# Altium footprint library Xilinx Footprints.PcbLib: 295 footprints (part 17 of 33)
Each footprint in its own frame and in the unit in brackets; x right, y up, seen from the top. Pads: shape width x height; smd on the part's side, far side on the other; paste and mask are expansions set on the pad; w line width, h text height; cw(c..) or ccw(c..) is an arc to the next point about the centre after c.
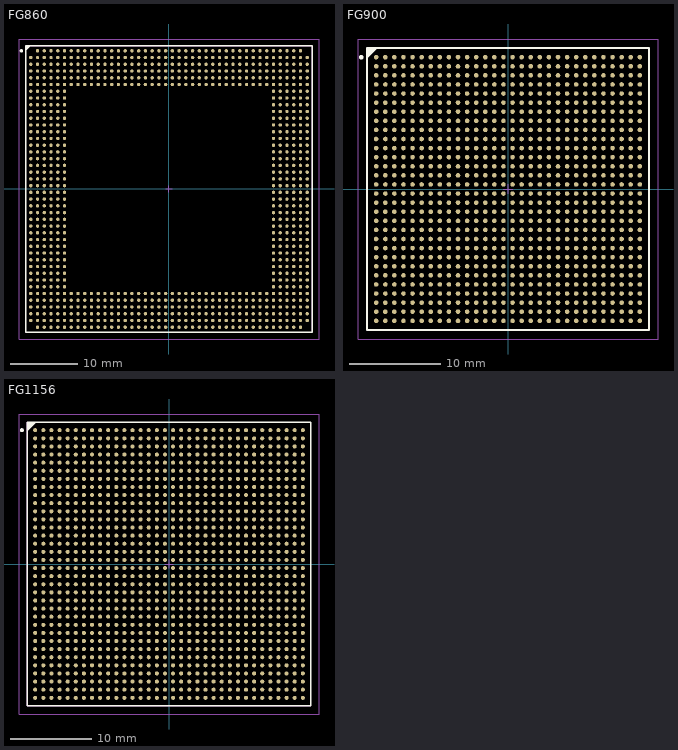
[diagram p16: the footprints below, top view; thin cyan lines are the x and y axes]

## FG860 [mm] "860-Ball Fine Pitch Ball Grid Array (FG860)"
height 2.3
pads (860):
  round 0.5 smd: A2(-19.5,20.5) A3(-18.5,20.5) A4(-17.5,20.5) A5(-16.5,20.5) A6(-15.5,20.5) A7(-14.5,20.5) A8(-13.5,20.5) A9(-12.5,20.5) A10(-11.5,20.5) A11(-10.5,20.5) A12(-9.5,20.5) A13(-8.5,20.5) A14(-7.5,20.5) A15(-6.5,20.5) A16(-5.5,20.5) A17(-4.5,20.5) A18(-3.5,20.5) A19(-2.5,20.5) A20(-1.5,20.5) A21(-0.5,20.5) A22(0.5,20.5) A23(1.5,20.5) A24(2.5,20.5) A25(3.5,20.5) A26(4.5,20.5) A27(5.5,20.5) A28(6.5,20.5) A29(7.5,20.5) A30(8.5,20.5) A31(9.5,20.5) A32(10.5,20.5) A33(11.5,20.5) A34(12.5,20.5) A35(13.5,20.5) A36(14.5,20.5) A37(15.5,20.5) A38(16.5,20.5) A39(17.5,20.5) A40(18.5,20.5) A41(19.5,20.5) AA1(-20.5,0.5) AA2(-19.5,0.5) AA3(-18.5,0.5) AA4(-17.5,0.5) AA5(-16.5,0.5) AA6(-15.5,0.5) AA37(15.5,0.5) AA38(16.5,0.5) AA39(17.5,0.5) AA40(18.5,0.5) AA41(19.5,0.5) AA42(20.5,0.5) AB1(-20.5,-0.5) AB2(-19.5,-0.5) AB3(-18.5,-0.5) AB4(-17.5,-0.5) AB5(-16.5,-0.5) AB6(-15.5,-0.5) AB37(15.5,-0.5) AB38(16.5,-0.5) AB39(17.5,-0.5) AB40(18.5,-0.5) AB41(19.5,-0.5) AB42(20.5,-0.5) AC1(-20.5,-1.5) AC2(-19.5,-1.5) AC3(-18.5,-1.5) AC4(-17.5,-1.5) AC5(-16.5,-1.5) AC6(-15.5,-1.5) AC37(15.5,-1.5) AC38(16.5,-1.5) AC39(17.5,-1.5) AC40(18.5,-1.5) AC41(19.5,-1.5) AC42(20.5,-1.5) AD1(-20.5,-2.5) AD2(-19.5,-2.5) AD3(-18.5,-2.5) AD4(-17.5,-2.5) AD5(-16.5,-2.5) AD6(-15.5,-2.5) AD37(15.5,-2.5) AD38(16.5,-2.5) AD39(17.5,-2.5) AD40(18.5,-2.5) AD41(19.5,-2.5) AD42(20.5,-2.5) AE1(-20.5,-3.5) AE2(-19.5,-3.5) AE3(-18.5,-3.5) AE4(-17.5,-3.5) AE5(-16.5,-3.5) AE6(-15.5,-3.5) AE37(15.5,-3.5) AE38(16.5,-3.5) AE39(17.5,-3.5) AE40(18.5,-3.5) AE41(19.5,-3.5) AE42(20.5,-3.5) AF1(-20.5,-4.5) AF2(-19.5,-4.5) AF3(-18.5,-4.5) AF4(-17.5,-4.5) AF5(-16.5,-4.5) AF6(-15.5,-4.5) AF37(15.5,-4.5) AF38(16.5,-4.5) AF39(17.5,-4.5) AF40(18.5,-4.5) AF41(19.5,-4.5) AF42(20.5,-4.5) AG1(-20.5,-5.5) AG2(-19.5,-5.5) AG3(-18.5,-5.5) AG4(-17.5,-5.5) AG5(-16.5,-5.5) AG6(-15.5,-5.5) AG37(15.5,-5.5) AG38(16.5,-5.5) AG39(17.5,-5.5) AG40(18.5,-5.5) AG41(19.5,-5.5) AG42(20.5,-5.5) AH1(-20.5,-6.5) AH2(-19.5,-6.5) AH3(-18.5,-6.5) AH4(-17.5,-6.5) AH5(-16.5,-6.5) AH6(-15.5,-6.5) AH37(15.5,-6.5) AH38(16.5,-6.5) AH39(17.5,-6.5) AH40(18.5,-6.5) AH41(19.5,-6.5) AH42(20.5,-6.5) AJ1(-20.5,-7.5) AJ2(-19.5,-7.5) AJ3(-18.5,-7.5) AJ4(-17.5,-7.5) AJ5(-16.5,-7.5) AJ6(-15.5,-7.5) AJ37(15.5,-7.5) AJ38(16.5,-7.5) AJ39(17.5,-7.5) AJ40(18.5,-7.5) AJ41(19.5,-7.5) AJ42(20.5,-7.5) AK1(-20.5,-8.5) AK2(-19.5,-8.5) AK3(-18.5,-8.5) AK4(-17.5,-8.5) AK5(-16.5,-8.5) AK6(-15.5,-8.5) AK37(15.5,-8.5) AK38(16.5,-8.5) AK39(17.5,-8.5) AK40(18.5,-8.5) AK41(19.5,-8.5) AK42(20.5,-8.5) AL1(-20.5,-9.5) AL2(-19.5,-9.5) AL3(-18.5,-9.5) AL4(-17.5,-9.5) AL5(-16.5,-9.5) AL6(-15.5,-9.5) AL37(15.5,-9.5) AL38(16.5,-9.5) AL39(17.5,-9.5) AL40(18.5,-9.5) AL41(19.5,-9.5) AL42(20.5,-9.5) AM1(-20.5,-10.5) AM2(-19.5,-10.5) AM3(-18.5,-10.5) AM4(-17.5,-10.5) AM5(-16.5,-10.5) AM6(-15.5,-10.5) AM37(15.5,-10.5) AM38(16.5,-10.5) AM39(17.5,-10.5) AM40(18.5,-10.5) AM41(19.5,-10.5) AM42(20.5,-10.5) AN1(-20.5,-11.5) AN2(-19.5,-11.5) AN3(-18.5,-11.5) AN4(-17.5,-11.5) AN5(-16.5,-11.5) AN6(-15.5,-11.5) AN37(15.5,-11.5) AN38(16.5,-11.5) AN39(17.5,-11.5) AN40(18.5,-11.5) AN41(19.5,-11.5) AN42(20.5,-11.5) AP1(-20.5,-12.5) AP2(-19.5,-12.5) AP3(-18.5,-12.5) AP4(-17.5,-12.5) AP5(-16.5,-12.5) AP6(-15.5,-12.5) AP37(15.5,-12.5) AP38(16.5,-12.5) AP39(17.5,-12.5) AP40(18.5,-12.5) AP41(19.5,-12.5) AP42(20.5,-12.5) AR1(-20.5,-13.5) AR2(-19.5,-13.5) AR3(-18.5,-13.5) AR4(-17.5,-13.5) AR5(-16.5,-13.5) AR6(-15.5,-13.5) AR37(15.5,-13.5) AR38(16.5,-13.5) AR39(17.5,-13.5) AR40(18.5,-13.5) AR41(19.5,-13.5) AR42(20.5,-13.5) AT1(-20.5,-14.5) AT2(-19.5,-14.5) AT3(-18.5,-14.5) AT4(-17.5,-14.5) AT5(-16.5,-14.5) AT6(-15.5,-14.5) AT37(15.5,-14.5) AT38(16.5,-14.5) AT39(17.5,-14.5) AT40(18.5,-14.5) AT41(19.5,-14.5) AT42(20.5,-14.5) AU1(-20.5,-15.5) AU2(-19.5,-15.5) AU3(-18.5,-15.5) AU4(-17.5,-15.5) AU5(-16.5,-15.5) AU6(-15.5,-15.5) AU7(-14.5,-15.5) AU8(-13.5,-15.5) AU9(-12.5,-15.5) AU10(-11.5,-15.5) AU11(-10.5,-15.5) AU12(-9.5,-15.5) AU13(-8.5,-15.5) AU14(-7.5,-15.5) AU15(-6.5,-15.5) AU16(-5.5,-15.5) AU17(-4.5,-15.5) AU18(-3.5,-15.5) AU19(-2.5,-15.5) AU20(-1.5,-15.5) AU21(-0.5,-15.5) AU22(0.5,-15.5) AU23(1.5,-15.5) AU24(2.5,-15.5) AU25(3.5,-15.5) AU26(4.5,-15.5) AU27(5.5,-15.5) AU28(6.5,-15.5) AU29(7.5,-15.5) AU30(8.5,-15.5) AU31(9.5,-15.5) AU32(10.5,-15.5) AU33(11.5,-15.5) AU34(12.5,-15.5) AU35(13.5,-15.5) AU36(14.5,-15.5) AU37(15.5,-15.5) AU38(16.5,-15.5) AU39(17.5,-15.5) AU40(18.5,-15.5) AU41(19.5,-15.5) AU42(20.5,-15.5) AV1(-20.5,-16.5) AV2(-19.5,-16.5) AV3(-18.5,-16.5) AV4(-17.5,-16.5) AV5(-16.5,-16.5) AV6(-15.5,-16.5) AV7(-14.5,-16.5) AV8(-13.5,-16.5) AV9(-12.5,-16.5) AV10(-11.5,-16.5) AV11(-10.5,-16.5) AV12(-9.5,-16.5) AV13(-8.5,-16.5) AV14(-7.5,-16.5) AV15(-6.5,-16.5) AV16(-5.5,-16.5) AV17(-4.5,-16.5) AV18(-3.5,-16.5) AV19(-2.5,-16.5) AV20(-1.5,-16.5) AV21(-0.5,-16.5) AV22(0.5,-16.5) AV23(1.5,-16.5) AV24(2.5,-16.5) AV25(3.5,-16.5) AV26(4.5,-16.5) AV27(5.5,-16.5) AV28(6.5,-16.5) AV29(7.5,-16.5) AV30(8.5,-16.5) AV31(9.5,-16.5) AV32(10.5,-16.5) AV33(11.5,-16.5) AV34(12.5,-16.5) AV35(13.5,-16.5) AV36(14.5,-16.5) AV37(15.5,-16.5) AV38(16.5,-16.5) AV39(17.5,-16.5) AV40(18.5,-16.5) AV41(19.5,-16.5) AV42(20.5,-16.5) AW1(-20.5,-17.5) AW2(-19.5,-17.5) AW3(-18.5,-17.5) AW4(-17.5,-17.5) AW5(-16.5,-17.5) AW6(-15.5,-17.5) AW7(-14.5,-17.5) AW8(-13.5,-17.5) AW9(-12.5,-17.5) AW10(-11.5,-17.5) AW11(-10.5,-17.5) AW12(-9.5,-17.5) AW13(-8.5,-17.5) AW14(-7.5,-17.5) AW15(-6.5,-17.5) AW16(-5.5,-17.5) AW17(-4.5,-17.5) AW18(-3.5,-17.5) AW19(-2.5,-17.5) AW20(-1.5,-17.5) AW21(-0.5,-17.5) AW22(0.5,-17.5) AW23(1.5,-17.5) AW24(2.5,-17.5) AW25(3.5,-17.5) AW26(4.5,-17.5) AW27(5.5,-17.5) AW28(6.5,-17.5) AW29(7.5,-17.5) AW30(8.5,-17.5) AW31(9.5,-17.5) AW32(10.5,-17.5) AW33(11.5,-17.5) AW34(12.5,-17.5) AW35(13.5,-17.5) AW36(14.5,-17.5) AW37(15.5,-17.5) AW38(16.5,-17.5) AW39(17.5,-17.5) AW40(18.5,-17.5) AW41(19.5,-17.5) AW42(20.5,-17.5) AY1(-20.5,-18.5) AY2(-19.5,-18.5) AY3(-18.5,-18.5) AY4(-17.5,-18.5) AY5(-16.5,-18.5) AY6(-15.5,-18.5) AY7(-14.5,-18.5) AY8(-13.5,-18.5) AY9(-12.5,-18.5) AY10(-11.5,-18.5) AY11(-10.5,-18.5) AY12(-9.5,-18.5) AY13(-8.5,-18.5) AY14(-7.5,-18.5) AY15(-6.5,-18.5) AY16(-5.5,-18.5) AY17(-4.5,-18.5) AY18(-3.5,-18.5) AY19(-2.5,-18.5) AY20(-1.5,-18.5) AY21(-0.5,-18.5) AY22(0.5,-18.5) AY23(1.5,-18.5) AY24(2.5,-18.5) AY25(3.5,-18.5) AY26(4.5,-18.5) AY27(5.5,-18.5) AY28(6.5,-18.5) AY29(7.5,-18.5) AY30(8.5,-18.5) AY31(9.5,-18.5) AY32(10.5,-18.5) AY33(11.5,-18.5) AY34(12.5,-18.5) AY35(13.5,-18.5) AY36(14.5,-18.5) AY37(15.5,-18.5) AY38(16.5,-18.5) AY39(17.5,-18.5) AY40(18.5,-18.5) AY41(19.5,-18.5) AY42(20.5,-18.5) B1(-20.5,19.5) B2(-19.5,19.5) B3(-18.5,19.5) B4(-17.5,19.5) B5(-16.5,19.5) B6(-15.5,19.5) B7(-14.5,19.5) B8(-13.5,19.5) B9(-12.5,19.5) B10(-11.5,19.5) B11(-10.5,19.5) B12(-9.5,19.5) B13(-8.5,19.5) B14(-7.5,19.5) B15(-6.5,19.5) B16(-5.5,19.5) B17(-4.5,19.5) B18(-3.5,19.5) B19(-2.5,19.5) B20(-1.5,19.5) B21(-0.5,19.5) B22(0.5,19.5) B23(1.5,19.5) B24(2.5,19.5) B25(3.5,19.5) B26(4.5,19.5) B27(5.5,19.5) B28(6.5,19.5) B29(7.5,19.5) B30(8.5,19.5) B31(9.5,19.5) B32(10.5,19.5) B33(11.5,19.5) B34(12.5,19.5) B35(13.5,19.5) B36(14.5,19.5) B37(15.5,19.5) B38(16.5,19.5) B39(17.5,19.5) B40(18.5,19.5) B41(19.5,19.5) B42(20.5,19.5) BA1(-20.5,-19.5) BA2(-19.5,-19.5) BA3(-18.5,-19.5) BA4(-17.5,-19.5) BA5(-16.5,-19.5) BA6(-15.5,-19.5) BA7(-14.5,-19.5) BA8(-13.5,-19.5) BA9(-12.5,-19.5) BA10(-11.5,-19.5) BA11(-10.5,-19.5) BA12(-9.5,-19.5) BA13(-8.5,-19.5) BA14(-7.5,-19.5) BA15(-6.5,-19.5) BA16(-5.5,-19.5) BA17(-4.5,-19.5) BA18(-3.5,-19.5) BA19(-2.5,-19.5) BA20(-1.5,-19.5) BA21(-0.5,-19.5) BA22(0.5,-19.5) BA23(1.5,-19.5) BA24(2.5,-19.5) BA25(3.5,-19.5) BA26(4.5,-19.5) BA27(5.5,-19.5) BA28(6.5,-19.5) BA29(7.5,-19.5) BA30(8.5,-19.5) BA31(9.5,-19.5) BA32(10.5,-19.5) BA33(11.5,-19.5) BA34(12.5,-19.5) BA35(13.5,-19.5) BA36(14.5,-19.5) BA37(15.5,-19.5) BA38(16.5,-19.5) BA39(17.5,-19.5) BA40(18.5,-19.5) BA41(19.5,-19.5) BA42(20.5,-19.5) BB2(-19.5,-20.5) BB3(-18.5,-20.5) BB4(-17.5,-20.5) BB5(-16.5,-20.5) BB6(-15.5,-20.5) BB7(-14.5,-20.5) BB8(-13.5,-20.5) BB9(-12.5,-20.5) BB10(-11.5,-20.5) BB11(-10.5,-20.5) BB12(-9.5,-20.5) BB13(-8.5,-20.5) BB14(-7.5,-20.5) BB15(-6.5,-20.5) BB16(-5.5,-20.5) BB17(-4.5,-20.5) BB18(-3.5,-20.5) BB19(-2.5,-20.5) BB20(-1.5,-20.5) BB21(-0.5,-20.5) BB22(0.5,-20.5) BB23(1.5,-20.5) BB24(2.5,-20.5) BB25(3.5,-20.5) BB26(4.5,-20.5) BB27(5.5,-20.5) BB28(6.5,-20.5) BB29(7.5,-20.5) BB30(8.5,-20.5) BB31(9.5,-20.5) BB32(10.5,-20.5) BB33(11.5,-20.5) BB34(12.5,-20.5) BB35(13.5,-20.5) BB36(14.5,-20.5) BB37(15.5,-20.5) BB38(16.5,-20.5) BB39(17.5,-20.5) BB40(18.5,-20.5) BB41(19.5,-20.5) C1(-20.5,18.5) C2(-19.5,18.5) C3(-18.5,18.5) C4(-17.5,18.5) C5(-16.5,18.5) C6(-15.5,18.5) C7(-14.5,18.5) C8(-13.5,18.5) C9(-12.5,18.5) C10(-11.5,18.5) C11(-10.5,18.5) C12(-9.5,18.5) C13(-8.5,18.5) C14(-7.5,18.5) C15(-6.5,18.5) C16(-5.5,18.5) C17(-4.5,18.5) C18(-3.5,18.5) C19(-2.5,18.5) C20(-1.5,18.5) C21(-0.5,18.5) C22(0.5,18.5) C23(1.5,18.5) C24(2.5,18.5) C25(3.5,18.5) C26(4.5,18.5) C27(5.5,18.5) C28(6.5,18.5) C29(7.5,18.5) C30(8.5,18.5) C31(9.5,18.5) C32(10.5,18.5) C33(11.5,18.5) C34(12.5,18.5) C35(13.5,18.5) C36(14.5,18.5) C37(15.5,18.5) C38(16.5,18.5) C39(17.5,18.5) C40(18.5,18.5) C41(19.5,18.5) C42(20.5,18.5) D1(-20.5,17.5) D2(-19.5,17.5) D3(-18.5,17.5) D4(-17.5,17.5) D5(-16.5,17.5) D6(-15.5,17.5) D7(-14.5,17.5) D8(-13.5,17.5) D9(-12.5,17.5) D10(-11.5,17.5) D11(-10.5,17.5) D12(-9.5,17.5) D13(-8.5,17.5) D14(-7.5,17.5) D15(-6.5,17.5) D16(-5.5,17.5) D17(-4.5,17.5) D18(-3.5,17.5) D19(-2.5,17.5) D20(-1.5,17.5) D21(-0.5,17.5) D22(0.5,17.5) D23(1.5,17.5) D24(2.5,17.5) D25(3.5,17.5) D26(4.5,17.5) D27(5.5,17.5) D28(6.5,17.5) D29(7.5,17.5) D30(8.5,17.5) D31(9.5,17.5) D32(10.5,17.5) D33(11.5,17.5) D34(12.5,17.5) D35(13.5,17.5) D36(14.5,17.5) D37(15.5,17.5) D38(16.5,17.5) D39(17.5,17.5) D40(18.5,17.5) D41(19.5,17.5) D42(20.5,17.5) E1(-20.5,16.5) E2(-19.5,16.5) E3(-18.5,16.5) E4(-17.5,16.5) E5(-16.5,16.5) E6(-15.5,16.5) E7(-14.5,16.5) E8(-13.5,16.5) E9(-12.5,16.5) E10(-11.5,16.5) E11(-10.5,16.5) E12(-9.5,16.5) E13(-8.5,16.5) E14(-7.5,16.5) E15(-6.5,16.5) E16(-5.5,16.5) E17(-4.5,16.5) E18(-3.5,16.5) E19(-2.5,16.5) E20(-1.5,16.5) E21(-0.5,16.5) E22(0.5,16.5) E23(1.5,16.5) E24(2.5,16.5) E25(3.5,16.5) E26(4.5,16.5) E27(5.5,16.5) E28(6.5,16.5) E29(7.5,16.5) E30(8.5,16.5) E31(9.5,16.5) E32(10.5,16.5) E33(11.5,16.5) E34(12.5,16.5) E35(13.5,16.5) E36(14.5,16.5) E37(15.5,16.5) E38(16.5,16.5) E39(17.5,16.5) E40(18.5,16.5) E41(19.5,16.5) E42(20.5,16.5) F1(-20.5,15.5) F2(-19.5,15.5) F3(-18.5,15.5) F4(-17.5,15.5) F5(-16.5,15.5) F6(-15.5,15.5) F7(-14.5,15.5) F8(-13.5,15.5) F9(-12.5,15.5) F10(-11.5,15.5) F11(-10.5,15.5) F12(-9.5,15.5) F13(-8.5,15.5) F14(-7.5,15.5) F15(-6.5,15.5) F16(-5.5,15.5) F17(-4.5,15.5) F18(-3.5,15.5) F19(-2.5,15.5) F20(-1.5,15.5) F21(-0.5,15.5) F22(0.5,15.5) F23(1.5,15.5) F24(2.5,15.5) F25(3.5,15.5) F26(4.5,15.5) F27(5.5,15.5) F28(6.5,15.5) F29(7.5,15.5) F30(8.5,15.5) F31(9.5,15.5) F32(10.5,15.5) F33(11.5,15.5) F34(12.5,15.5) F35(13.5,15.5) F36(14.5,15.5) F37(15.5,15.5) F38(16.5,15.5) F39(17.5,15.5) F40(18.5,15.5) F41(19.5,15.5) F42(20.5,15.5) G1(-20.5,14.5) G2(-19.5,14.5) G3(-18.5,14.5) G4(-17.5,14.5) G5(-16.5,14.5) G6(-15.5,14.5) G37(15.5,14.5) G38(16.5,14.5) G39(17.5,14.5) G40(18.5,14.5) G41(19.5,14.5) G42(20.5,14.5) H1(-20.5,13.5) H2(-19.5,13.5) H3(-18.5,13.5) H4(-17.5,13.5) H5(-16.5,13.5) H6(-15.5,13.5) H37(15.5,13.5) H38(16.5,13.5) H39(17.5,13.5) H40(18.5,13.5) H41(19.5,13.5) H42(20.5,13.5) J1(-20.5,12.5) J2(-19.5,12.5) J3(-18.5,12.5) J4(-17.5,12.5) J5(-16.5,12.5) J6(-15.5,12.5) J37(15.5,12.5) J38(16.5,12.5) J39(17.5,12.5) J40(18.5,12.5) J41(19.5,12.5) J42(20.5,12.5) K1(-20.5,11.5) K2(-19.5,11.5) K3(-18.5,11.5) K4(-17.5,11.5) K5(-16.5,11.5) K6(-15.5,11.5) K37(15.5,11.5) K38(16.5,11.5) K39(17.5,11.5) K40(18.5,11.5) K41(19.5,11.5) K42(20.5,11.5) L1(-20.5,10.5) L2(-19.5,10.5) L3(-18.5,10.5) L4(-17.5,10.5) L5(-16.5,10.5) L6(-15.5,10.5) L37(15.5,10.5) L38(16.5,10.5) L39(17.5,10.5) L40(18.5,10.5) L41(19.5,10.5) L42(20.5,10.5) M1(-20.5,9.5) M2(-19.5,9.5) M3(-18.5,9.5) M4(-17.5,9.5) M5(-16.5,9.5) M6(-15.5,9.5) M37(15.5,9.5) M38(16.5,9.5) M39(17.5,9.5) M40(18.5,9.5) M41(19.5,9.5) M42(20.5,9.5) N1(-20.5,8.5) N2(-19.5,8.5) N3(-18.5,8.5) N4(-17.5,8.5) N5(-16.5,8.5) N6(-15.5,8.5) N37(15.5,8.5) N38(16.5,8.5) N39(17.5,8.5) N40(18.5,8.5) N41(19.5,8.5) N42(20.5,8.5) P1(-20.5,7.5) P2(-19.5,7.5) P3(-18.5,7.5) P4(-17.5,7.5) P5(-16.5,7.5) P6(-15.5,7.5) P37(15.5,7.5) P38(16.5,7.5) P39(17.5,7.5) P40(18.5,7.5) P41(19.5,7.5) P42(20.5,7.5) R1(-20.5,6.5) R2(-19.5,6.5) R3(-18.5,6.5) R4(-17.5,6.5) R5(-16.5,6.5) R6(-15.5,6.5) R37(15.5,6.5) R38(16.5,6.5) R39(17.5,6.5) R40(18.5,6.5) R41(19.5,6.5) R42(20.5,6.5) T1(-20.5,5.5) T2(-19.5,5.5) T3(-18.5,5.5) T4(-17.5,5.5) T5(-16.5,5.5) T6(-15.5,5.5) T37(15.5,5.5) T38(16.5,5.5) T39(17.5,5.5) T40(18.5,5.5) T41(19.5,5.5) T42(20.5,5.5) U1(-20.5,4.5) U2(-19.5,4.5) U3(-18.5,4.5) U4(-17.5,4.5) U5(-16.5,4.5) U6(-15.5,4.5) U37(15.5,4.5) U38(16.5,4.5) U39(17.5,4.5) U40(18.5,4.5) U41(19.5,4.5) U42(20.5,4.5) V1(-20.5,3.5) V2(-19.5,3.5) V3(-18.5,3.5) V4(-17.5,3.5) V5(-16.5,3.5) V6(-15.5,3.5) V37(15.5,3.5) V38(16.5,3.5) V39(17.5,3.5) V40(18.5,3.5) V41(19.5,3.5) V42(20.5,3.5) W1(-20.5,2.5) W2(-19.5,2.5) W3(-18.5,2.5) W4(-17.5,2.5) W5(-16.5,2.5) W6(-15.5,2.5) W37(15.5,2.5) W38(16.5,2.5) W39(17.5,2.5) W40(18.5,2.5) W41(19.5,2.5) W42(20.5,2.5) Y1(-20.5,1.5) Y2(-19.5,1.5) Y3(-18.5,1.5) Y4(-17.5,1.5) Y5(-16.5,1.5) Y6(-15.5,1.5) Y37(15.5,1.5) Y38(16.5,1.5) Y39(17.5,1.5) Y40(18.5,1.5) Y41(19.5,1.5) Y42(20.5,1.5)
Top Overlay:
  circle w0.25: c-21.9,20.5 r0.125
  region: -20.669,21.25 -21.25,20.669 -21.25,21.25
  lines w0.2: -21.25,20.669 -20.669,21.25 ; -21.25,-21.25 21.25,-21.25 21.25,21.25 -21.25,21.25 -21.25,-21.25
Mechanical 13:
  lines w0.1: -21.25,-21.25 21.25,-21.25 21.25,21.25 -21.25,21.25 -21.25,-21.25
Mechanical 15:
  lines w0.1: -0.5,0 0.5,0 ; 0,-0.5 0,0.5 ; -22.25,-22.25 22.25,-22.25 22.25,22.25 -22.25,22.25 -22.25,-22.25
3D body: height 2.3, standoff 0, extent -21.25,-21.25 21.25,21.25

## FG900 [mm] "900-Ball Fine Pitch Ball Grid Array (FG900)"
height 2.6
pads (900):
  round 0.5 smd: A1(-14.5,14.5) A2(-13.5,14.5) A3(-12.5,14.5) A4(-11.5,14.5) A5(-10.5,14.5) A6(-9.5,14.5) A7(-8.5,14.5) A8(-7.5,14.5) A9(-6.5,14.5) A10(-5.5,14.5) A11(-4.5,14.5) A12(-3.5,14.5) A13(-2.5,14.5) A14(-1.5,14.5) A15(-0.5,14.5) A16(0.5,14.5) A17(1.5,14.5) A18(2.5,14.5) A19(3.5,14.5) A20(4.5,14.5) A21(5.5,14.5) A22(6.5,14.5) A23(7.5,14.5) A24(8.5,14.5) A25(9.5,14.5) A26(10.5,14.5) A27(11.5,14.5) A28(12.5,14.5) A29(13.5,14.5) A30(14.5,14.5) AA1(-14.5,-5.5) AA2(-13.5,-5.5) AA3(-12.5,-5.5) AA4(-11.5,-5.5) AA5(-10.5,-5.5) AA6(-9.5,-5.5) AA7(-8.5,-5.5) AA8(-7.5,-5.5) AA9(-6.5,-5.5) AA10(-5.5,-5.5) AA11(-4.5,-5.5) AA12(-3.5,-5.5) AA13(-2.5,-5.5) AA14(-1.5,-5.5) AA15(-0.5,-5.5) AA16(0.5,-5.5) AA17(1.5,-5.5) AA18(2.5,-5.5) AA19(3.5,-5.5) AA20(4.5,-5.5) AA21(5.5,-5.5) AA22(6.5,-5.5) AA23(7.5,-5.5) AA24(8.5,-5.5) AA25(9.5,-5.5) AA26(10.5,-5.5) AA27(11.5,-5.5) AA28(12.5,-5.5) AA29(13.5,-5.5) AA30(14.5,-5.5) AB1(-14.5,-6.5) AB2(-13.5,-6.5) AB3(-12.5,-6.5) AB4(-11.5,-6.5) AB5(-10.5,-6.5) AB6(-9.5,-6.5) AB7(-8.5,-6.5) AB8(-7.5,-6.5) AB9(-6.5,-6.5) AB10(-5.5,-6.5) AB11(-4.5,-6.5) AB12(-3.5,-6.5) AB13(-2.5,-6.5) AB14(-1.5,-6.5) AB15(-0.5,-6.5) AB16(0.5,-6.5) AB17(1.5,-6.5) AB18(2.5,-6.5) AB19(3.5,-6.5) AB20(4.5,-6.5) AB21(5.5,-6.5) AB22(6.5,-6.5) AB23(7.5,-6.5) AB24(8.5,-6.5) AB25(9.5,-6.5) AB26(10.5,-6.5) AB27(11.5,-6.5) AB28(12.5,-6.5) AB29(13.5,-6.5) AB30(14.5,-6.5) AC1(-14.5,-7.5) AC2(-13.5,-7.5) AC3(-12.5,-7.5) AC4(-11.5,-7.5) AC5(-10.5,-7.5) AC6(-9.5,-7.5) AC7(-8.5,-7.5) AC8(-7.5,-7.5) AC9(-6.5,-7.5) AC10(-5.5,-7.5) AC11(-4.5,-7.5) AC12(-3.5,-7.5) AC13(-2.5,-7.5) AC14(-1.5,-7.5) AC15(-0.5,-7.5) AC16(0.5,-7.5) AC17(1.5,-7.5) AC18(2.5,-7.5) AC19(3.5,-7.5) AC20(4.5,-7.5) AC21(5.5,-7.5) AC22(6.5,-7.5) AC23(7.5,-7.5) AC24(8.5,-7.5) AC25(9.5,-7.5) AC26(10.5,-7.5) AC27(11.5,-7.5) AC28(12.5,-7.5) AC29(13.5,-7.5) AC30(14.5,-7.5) AD1(-14.5,-8.5) AD2(-13.5,-8.5) AD3(-12.5,-8.5) AD4(-11.5,-8.5) AD5(-10.5,-8.5) AD6(-9.5,-8.5) AD7(-8.5,-8.5) AD8(-7.5,-8.5) AD9(-6.5,-8.5) AD10(-5.5,-8.5) AD11(-4.5,-8.5) AD12(-3.5,-8.5) AD13(-2.5,-8.5) AD14(-1.5,-8.5) AD15(-0.5,-8.5) AD16(0.5,-8.5) AD17(1.5,-8.5) AD18(2.5,-8.5) AD19(3.5,-8.5) AD20(4.5,-8.5) AD21(5.5,-8.5) AD22(6.5,-8.5) AD23(7.5,-8.5) AD24(8.5,-8.5) AD25(9.5,-8.5) AD26(10.5,-8.5) AD27(11.5,-8.5) AD28(12.5,-8.5) AD29(13.5,-8.5) AD30(14.5,-8.5) AE1(-14.5,-9.5) AE2(-13.5,-9.5) AE3(-12.5,-9.5) AE4(-11.5,-9.5) AE5(-10.5,-9.5) AE6(-9.5,-9.5) AE7(-8.5,-9.5) AE8(-7.5,-9.5) AE9(-6.5,-9.5) AE10(-5.5,-9.5) AE11(-4.5,-9.5) AE12(-3.5,-9.5) AE13(-2.5,-9.5) AE14(-1.5,-9.5) AE15(-0.5,-9.5) AE16(0.5,-9.5) AE17(1.5,-9.5) AE18(2.5,-9.5) AE19(3.5,-9.5) AE20(4.5,-9.5) AE21(5.5,-9.5) AE22(6.5,-9.5) AE23(7.5,-9.5) AE24(8.5,-9.5) AE25(9.5,-9.5) AE26(10.5,-9.5) AE27(11.5,-9.5) AE28(12.5,-9.5) AE29(13.5,-9.5) AE30(14.5,-9.5) AF1(-14.5,-10.5) AF2(-13.5,-10.5) AF3(-12.5,-10.5) AF4(-11.5,-10.5) AF5(-10.5,-10.5) AF6(-9.5,-10.5) AF7(-8.5,-10.5) AF8(-7.5,-10.5) AF9(-6.5,-10.5) AF10(-5.5,-10.5) AF11(-4.5,-10.5) AF12(-3.5,-10.5) AF13(-2.5,-10.5) AF14(-1.5,-10.5) AF15(-0.5,-10.5) AF16(0.5,-10.5) AF17(1.5,-10.5) AF18(2.5,-10.5) AF19(3.5,-10.5) AF20(4.5,-10.5) AF21(5.5,-10.5) AF22(6.5,-10.5) AF23(7.5,-10.5) AF24(8.5,-10.5) AF25(9.5,-10.5) AF26(10.5,-10.5) AF27(11.5,-10.5) AF28(12.5,-10.5) AF29(13.5,-10.5) AF30(14.5,-10.5) AG1(-14.5,-11.5) AG2(-13.5,-11.5) AG3(-12.5,-11.5) AG4(-11.5,-11.5) AG5(-10.5,-11.5) AG6(-9.5,-11.5) AG7(-8.5,-11.5) AG8(-7.5,-11.5) AG9(-6.5,-11.5) AG10(-5.5,-11.5) AG11(-4.5,-11.5) AG12(-3.5,-11.5) AG13(-2.5,-11.5) AG14(-1.5,-11.5) AG15(-0.5,-11.5) AG16(0.5,-11.5) AG17(1.5,-11.5) AG18(2.5,-11.5) AG19(3.5,-11.5) AG20(4.5,-11.5) AG21(5.5,-11.5) AG22(6.5,-11.5) AG23(7.5,-11.5) AG24(8.5,-11.5) AG25(9.5,-11.5) AG26(10.5,-11.5) AG27(11.5,-11.5) AG28(12.5,-11.5) AG29(13.5,-11.5) AG30(14.5,-11.5) AH1(-14.5,-12.5) AH2(-13.5,-12.5) AH3(-12.5,-12.5) AH4(-11.5,-12.5) AH5(-10.5,-12.5) AH6(-9.5,-12.5) AH7(-8.5,-12.5) AH8(-7.5,-12.5) AH9(-6.5,-12.5) AH10(-5.5,-12.5) AH11(-4.5,-12.5) AH12(-3.5,-12.5) AH13(-2.5,-12.5) AH14(-1.5,-12.5) AH15(-0.5,-12.5) AH16(0.5,-12.5) AH17(1.5,-12.5) AH18(2.5,-12.5) AH19(3.5,-12.5) AH20(4.5,-12.5) AH21(5.5,-12.5) AH22(6.5,-12.5) AH23(7.5,-12.5) AH24(8.5,-12.5) AH25(9.5,-12.5) AH26(10.5,-12.5) AH27(11.5,-12.5) AH28(12.5,-12.5) AH29(13.5,-12.5) AH30(14.5,-12.5) AJ1(-14.5,-13.5) AJ2(-13.5,-13.5) AJ3(-12.5,-13.5) AJ4(-11.5,-13.5) AJ5(-10.5,-13.5) AJ6(-9.5,-13.5) AJ7(-8.5,-13.5) AJ8(-7.5,-13.5) AJ9(-6.5,-13.5) AJ10(-5.5,-13.5) AJ11(-4.5,-13.5) AJ12(-3.5,-13.5) AJ13(-2.5,-13.5) AJ14(-1.5,-13.5) AJ15(-0.5,-13.5) AJ16(0.5,-13.5) AJ17(1.5,-13.5) AJ18(2.5,-13.5) AJ19(3.5,-13.5) AJ20(4.5,-13.5) AJ21(5.5,-13.5) AJ22(6.5,-13.5) AJ23(7.5,-13.5) AJ24(8.5,-13.5) AJ25(9.5,-13.5) AJ26(10.5,-13.5) AJ27(11.5,-13.5) AJ28(12.5,-13.5) AJ29(13.5,-13.5) AJ30(14.5,-13.5) AK1(-14.5,-14.5) AK2(-13.5,-14.5) AK3(-12.5,-14.5) AK4(-11.5,-14.5) AK5(-10.5,-14.5) AK6(-9.5,-14.5) AK7(-8.5,-14.5) AK8(-7.5,-14.5) AK9(-6.5,-14.5) AK10(-5.5,-14.5) AK11(-4.5,-14.5) AK12(-3.5,-14.5) AK13(-2.5,-14.5) AK14(-1.5,-14.5) AK15(-0.5,-14.5) AK16(0.5,-14.5) AK17(1.5,-14.5) AK18(2.5,-14.5) AK19(3.5,-14.5) AK20(4.5,-14.5) AK21(5.5,-14.5) AK22(6.5,-14.5) AK23(7.5,-14.5) AK24(8.5,-14.5) AK25(9.5,-14.5) AK26(10.5,-14.5) AK27(11.5,-14.5) AK28(12.5,-14.5) AK29(13.5,-14.5) AK30(14.5,-14.5) B1(-14.5,13.5) B2(-13.5,13.5) B3(-12.5,13.5) B4(-11.5,13.5) B5(-10.5,13.5) B6(-9.5,13.5) B7(-8.5,13.5) B8(-7.5,13.5) B9(-6.5,13.5) B10(-5.5,13.5) B11(-4.5,13.5) B12(-3.5,13.5) B13(-2.5,13.5) B14(-1.5,13.5) B15(-0.5,13.5) B16(0.5,13.5) B17(1.5,13.5) B18(2.5,13.5) B19(3.5,13.5) B20(4.5,13.5) B21(5.5,13.5) B22(6.5,13.5) B23(7.5,13.5) B24(8.5,13.5) B25(9.5,13.5) B26(10.5,13.5) B27(11.5,13.5) B28(12.5,13.5) B29(13.5,13.5) B30(14.5,13.5) C1(-14.5,12.5) C2(-13.5,12.5) C3(-12.5,12.5) C4(-11.5,12.5) C5(-10.5,12.5) C6(-9.5,12.5) C7(-8.5,12.5) C8(-7.5,12.5) C9(-6.5,12.5) C10(-5.5,12.5) C11(-4.5,12.5) C12(-3.5,12.5) C13(-2.5,12.5) C14(-1.5,12.5) C15(-0.5,12.5) C16(0.5,12.5) C17(1.5,12.5) C18(2.5,12.5) C19(3.5,12.5) C20(4.5,12.5) C21(5.5,12.5) C22(6.5,12.5) C23(7.5,12.5) C24(8.5,12.5) C25(9.5,12.5) C26(10.5,12.5) C27(11.5,12.5) C28(12.5,12.5) C29(13.5,12.5) C30(14.5,12.5) D1(-14.5,11.5) D2(-13.5,11.5) D3(-12.5,11.5) D4(-11.5,11.5) D5(-10.5,11.5) D6(-9.5,11.5) D7(-8.5,11.5) D8(-7.5,11.5) D9(-6.5,11.5) D10(-5.5,11.5) D11(-4.5,11.5) D12(-3.5,11.5) D13(-2.5,11.5) D14(-1.5,11.5) D15(-0.5,11.5) D16(0.5,11.5) D17(1.5,11.5) D18(2.5,11.5) D19(3.5,11.5) D20(4.5,11.5) D21(5.5,11.5) D22(6.5,11.5) D23(7.5,11.5) D24(8.5,11.5) D25(9.5,11.5) D26(10.5,11.5) D27(11.5,11.5) D28(12.5,11.5) D29(13.5,11.5) D30(14.5,11.5) E1(-14.5,10.5) E2(-13.5,10.5) E3(-12.5,10.5) E4(-11.5,10.5) E5(-10.5,10.5) E6(-9.5,10.5) E7(-8.5,10.5) E8(-7.5,10.5) E9(-6.5,10.5) E10(-5.5,10.5) E11(-4.5,10.5) E12(-3.5,10.5) E13(-2.5,10.5) E14(-1.5,10.5) E15(-0.5,10.5) E16(0.5,10.5) E17(1.5,10.5) E18(2.5,10.5) E19(3.5,10.5) E20(4.5,10.5) E21(5.5,10.5) E22(6.5,10.5) E23(7.5,10.5) E24(8.5,10.5) E25(9.5,10.5) E26(10.5,10.5) E27(11.5,10.5) E28(12.5,10.5) E29(13.5,10.5) E30(14.5,10.5) F1(-14.5,9.5) F2(-13.5,9.5) F3(-12.5,9.5) F4(-11.5,9.5) F5(-10.5,9.5) F6(-9.5,9.5) F7(-8.5,9.5) F8(-7.5,9.5) F9(-6.5,9.5) F10(-5.5,9.5) F11(-4.5,9.5) F12(-3.5,9.5) F13(-2.5,9.5) F14(-1.5,9.5) F15(-0.5,9.5) F16(0.5,9.5) F17(1.5,9.5) F18(2.5,9.5) F19(3.5,9.5) F20(4.5,9.5) F21(5.5,9.5) F22(6.5,9.5) F23(7.5,9.5) F24(8.5,9.5) F25(9.5,9.5) F26(10.5,9.5) F27(11.5,9.5) F28(12.5,9.5) F29(13.5,9.5) F30(14.5,9.5) G1(-14.5,8.5) G2(-13.5,8.5) G3(-12.5,8.5) G4(-11.5,8.5) G5(-10.5,8.5) G6(-9.5,8.5) G7(-8.5,8.5) G8(-7.5,8.5) G9(-6.5,8.5) G10(-5.5,8.5) G11(-4.5,8.5) G12(-3.5,8.5) G13(-2.5,8.5) G14(-1.5,8.5) G15(-0.5,8.5) G16(0.5,8.5) G17(1.5,8.5) G18(2.5,8.5) G19(3.5,8.5) G20(4.5,8.5) G21(5.5,8.5) G22(6.5,8.5) G23(7.5,8.5) G24(8.5,8.5) G25(9.5,8.5) G26(10.5,8.5) G27(11.5,8.5) G28(12.5,8.5) G29(13.5,8.5) G30(14.5,8.5) H1(-14.5,7.5) H2(-13.5,7.5) H3(-12.5,7.5) H4(-11.5,7.5) H5(-10.5,7.5) H6(-9.5,7.5) H7(-8.5,7.5) H8(-7.5,7.5) H9(-6.5,7.5) H10(-5.5,7.5) H11(-4.5,7.5) H12(-3.5,7.5) H13(-2.5,7.5) H14(-1.5,7.5) H15(-0.5,7.5) H16(0.5,7.5) H17(1.5,7.5) H18(2.5,7.5) H19(3.5,7.5) H20(4.5,7.5) H21(5.5,7.5) H22(6.5,7.5) H23(7.5,7.5) H24(8.5,7.5) H25(9.5,7.5) H26(10.5,7.5) H27(11.5,7.5) H28(12.5,7.5) H29(13.5,7.5) H30(14.5,7.5) J1(-14.5,6.5) J2(-13.5,6.5) J3(-12.5,6.5) J4(-11.5,6.5) J5(-10.5,6.5) J6(-9.5,6.5) J7(-8.5,6.5) J8(-7.5,6.5) J9(-6.5,6.5) J10(-5.5,6.5) J11(-4.5,6.5) J12(-3.5,6.5) J13(-2.5,6.5) J14(-1.5,6.5) J15(-0.5,6.5) J16(0.5,6.5) J17(1.5,6.5) J18(2.5,6.5) J19(3.5,6.5) J20(4.5,6.5) J21(5.5,6.5) J22(6.5,6.5) J23(7.5,6.5) J24(8.5,6.5) J25(9.5,6.5) J26(10.5,6.5) J27(11.5,6.5) J28(12.5,6.5) J29(13.5,6.5) J30(14.5,6.5) K1(-14.5,5.5) K2(-13.5,5.5) K3(-12.5,5.5) K4(-11.5,5.5) K5(-10.5,5.5) K6(-9.5,5.5) K7(-8.5,5.5) K8(-7.5,5.5) K9(-6.5,5.5) K10(-5.5,5.5) K11(-4.5,5.5) K12(-3.5,5.5) K13(-2.5,5.5) K14(-1.5,5.5) K15(-0.5,5.5) K16(0.5,5.5) K17(1.5,5.5) K18(2.5,5.5) K19(3.5,5.5) K20(4.5,5.5) K21(5.5,5.5) K22(6.5,5.5) K23(7.5,5.5) K24(8.5,5.5) K25(9.5,5.5) K26(10.5,5.5) K27(11.5,5.5) K28(12.5,5.5) K29(13.5,5.5) K30(14.5,5.5) L1(-14.5,4.5) L2(-13.5,4.5) L3(-12.5,4.5) L4(-11.5,4.5) L5(-10.5,4.5) L6(-9.5,4.5) L7(-8.5,4.5) L8(-7.5,4.5) L9(-6.5,4.5) L10(-5.5,4.5) L11(-4.5,4.5) L12(-3.5,4.5) L13(-2.5,4.5) L14(-1.5,4.5) L15(-0.5,4.5) L16(0.5,4.5) L17(1.5,4.5) L18(2.5,4.5) L19(3.5,4.5) L20(4.5,4.5) L21(5.5,4.5) L22(6.5,4.5) L23(7.5,4.5) L24(8.5,4.5) L25(9.5,4.5) L26(10.5,4.5) L27(11.5,4.5) L28(12.5,4.5) L29(13.5,4.5) L30(14.5,4.5) M1(-14.5,3.5) M2(-13.5,3.5) M3(-12.5,3.5) M4(-11.5,3.5) M5(-10.5,3.5) M6(-9.5,3.5) M7(-8.5,3.5) M8(-7.5,3.5) M9(-6.5,3.5) M10(-5.5,3.5) M11(-4.5,3.5) M12(-3.5,3.5) M13(-2.5,3.5) M14(-1.5,3.5) M15(-0.5,3.5) M16(0.5,3.5) M17(1.5,3.5) M18(2.5,3.5) M19(3.5,3.5) M20(4.5,3.5) M21(5.5,3.5) M22(6.5,3.5) M23(7.5,3.5) M24(8.5,3.5) M25(9.5,3.5) M26(10.5,3.5) M27(11.5,3.5) M28(12.5,3.5) M29(13.5,3.5) M30(14.5,3.5) N1(-14.5,2.5) N2(-13.5,2.5) N3(-12.5,2.5) N4(-11.5,2.5) N5(-10.5,2.5) N6(-9.5,2.5) N7(-8.5,2.5) N8(-7.5,2.5) N9(-6.5,2.5) N10(-5.5,2.5) N11(-4.5,2.5) N12(-3.5,2.5) N13(-2.5,2.5) N14(-1.5,2.5) N15(-0.5,2.5) N16(0.5,2.5) N17(1.5,2.5) N18(2.5,2.5) N19(3.5,2.5) N20(4.5,2.5) N21(5.5,2.5) N22(6.5,2.5) N23(7.5,2.5) N24(8.5,2.5) N25(9.5,2.5) N26(10.5,2.5) N27(11.5,2.5) N28(12.5,2.5) N29(13.5,2.5) N30(14.5,2.5) P1(-14.5,1.5) P2(-13.5,1.5) P3(-12.5,1.5) P4(-11.5,1.5) P5(-10.5,1.5) P6(-9.5,1.5) P7(-8.5,1.5) P8(-7.5,1.5) P9(-6.5,1.5) P10(-5.5,1.5) P11(-4.5,1.5) P12(-3.5,1.5) P13(-2.5,1.5) P14(-1.5,1.5) P15(-0.5,1.5) P16(0.5,1.5) P17(1.5,1.5) P18(2.5,1.5) P19(3.5,1.5) P20(4.5,1.5) P21(5.5,1.5) P22(6.5,1.5) P23(7.5,1.5) P24(8.5,1.5) P25(9.5,1.5) P26(10.5,1.5) P27(11.5,1.5) P28(12.5,1.5) P29(13.5,1.5) P30(14.5,1.5) R1(-14.5,0.5) R2(-13.5,0.5) R3(-12.5,0.5) R4(-11.5,0.5) R5(-10.5,0.5) R6(-9.5,0.5) R7(-8.5,0.5) R8(-7.5,0.5) R9(-6.5,0.5) R10(-5.5,0.5) R11(-4.5,0.5) R12(-3.5,0.5) R13(-2.5,0.5) R14(-1.5,0.5) R15(-0.5,0.5) R16(0.5,0.5) R17(1.5,0.5) R18(2.5,0.5) R19(3.5,0.5) R20(4.5,0.5) R21(5.5,0.5) R22(6.5,0.5) R23(7.5,0.5) R24(8.5,0.5) R25(9.5,0.5) R26(10.5,0.5) R27(11.5,0.5) R28(12.5,0.5) R29(13.5,0.5) R30(14.5,0.5) T1(-14.5,-0.5) T2(-13.5,-0.5) T3(-12.5,-0.5) T4(-11.5,-0.5) T5(-10.5,-0.5) T6(-9.5,-0.5) T7(-8.5,-0.5) T8(-7.5,-0.5) T9(-6.5,-0.5) T10(-5.5,-0.5) T11(-4.5,-0.5) T12(-3.5,-0.5) T13(-2.5,-0.5) T14(-1.5,-0.5) T15(-0.5,-0.5) T16(0.5,-0.5) T17(1.5,-0.5) T18(2.5,-0.5) T19(3.5,-0.5) T20(4.5,-0.5) T21(5.5,-0.5) T22(6.5,-0.5) T23(7.5,-0.5) T24(8.5,-0.5) T25(9.5,-0.5) T26(10.5,-0.5) T27(11.5,-0.5) T28(12.5,-0.5) T29(13.5,-0.5) T30(14.5,-0.5) U1(-14.5,-1.5) U2(-13.5,-1.5) U3(-12.5,-1.5) U4(-11.5,-1.5) U5(-10.5,-1.5) U6(-9.5,-1.5) U7(-8.5,-1.5) U8(-7.5,-1.5) U9(-6.5,-1.5) U10(-5.5,-1.5) U11(-4.5,-1.5) U12(-3.5,-1.5) U13(-2.5,-1.5) U14(-1.5,-1.5) U15(-0.5,-1.5) U16(0.5,-1.5) U17(1.5,-1.5) U18(2.5,-1.5) U19(3.5,-1.5) U20(4.5,-1.5) U21(5.5,-1.5) U22(6.5,-1.5) U23(7.5,-1.5) U24(8.5,-1.5) U25(9.5,-1.5) U26(10.5,-1.5) U27(11.5,-1.5) U28(12.5,-1.5) U29(13.5,-1.5) U30(14.5,-1.5) V1(-14.5,-2.5) V2(-13.5,-2.5) V3(-12.5,-2.5) V4(-11.5,-2.5) V5(-10.5,-2.5) V6(-9.5,-2.5) V7(-8.5,-2.5) V8(-7.5,-2.5) V9(-6.5,-2.5) V10(-5.5,-2.5) V11(-4.5,-2.5) V12(-3.5,-2.5) V13(-2.5,-2.5) V14(-1.5,-2.5) V15(-0.5,-2.5) V16(0.5,-2.5) V17(1.5,-2.5) V18(2.5,-2.5) V19(3.5,-2.5) V20(4.5,-2.5) V21(5.5,-2.5) V22(6.5,-2.5) V23(7.5,-2.5) V24(8.5,-2.5) V25(9.5,-2.5) V26(10.5,-2.5) V27(11.5,-2.5) V28(12.5,-2.5) V29(13.5,-2.5) V30(14.5,-2.5) W1(-14.5,-3.5) W2(-13.5,-3.5) W3(-12.5,-3.5) W4(-11.5,-3.5) W5(-10.5,-3.5) W6(-9.5,-3.5) W7(-8.5,-3.5) W8(-7.5,-3.5) W9(-6.5,-3.5) W10(-5.5,-3.5) W11(-4.5,-3.5) W12(-3.5,-3.5) W13(-2.5,-3.5) W14(-1.5,-3.5) W15(-0.5,-3.5) W16(0.5,-3.5) W17(1.5,-3.5) W18(2.5,-3.5) W19(3.5,-3.5) W20(4.5,-3.5) W21(5.5,-3.5) W22(6.5,-3.5) W23(7.5,-3.5) W24(8.5,-3.5) W25(9.5,-3.5) W26(10.5,-3.5) W27(11.5,-3.5) W28(12.5,-3.5) W29(13.5,-3.5) W30(14.5,-3.5) Y1(-14.5,-4.5) Y2(-13.5,-4.5) Y3(-12.5,-4.5) Y4(-11.5,-4.5) Y5(-10.5,-4.5) Y6(-9.5,-4.5) Y7(-8.5,-4.5) Y8(-7.5,-4.5) Y9(-6.5,-4.5) Y10(-5.5,-4.5) Y11(-4.5,-4.5) Y12(-3.5,-4.5) Y13(-2.5,-4.5) Y14(-1.5,-4.5) Y15(-0.5,-4.5) Y16(0.5,-4.5) Y17(1.5,-4.5) Y18(2.5,-4.5) Y19(3.5,-4.5) Y20(4.5,-4.5) Y21(5.5,-4.5) Y22(6.5,-4.5) Y23(7.5,-4.5) Y24(8.5,-4.5) Y25(9.5,-4.5) Y26(10.5,-4.5) Y27(11.5,-4.5) Y28(12.5,-4.5) Y29(13.5,-4.5) Y30(14.5,-4.5)
Top Overlay:
  circle w0.25: c-16.15,14.5 r0.125
  region: -14.5,15.5 -15.5,14.5 -15.5,15.5
  lines w0.2: -15.5,14.5 -14.5,15.5 ; -15.5,-15.5 -15.5,15.5 15.5,15.5 15.5,-15.5 -15.5,-15.5
Mechanical 13:
  lines w0.1: -15.5,-15.5 -15.5,15.5 15.5,15.5 15.5,-15.5 -15.5,-15.5
Mechanical 15:
  lines w0.1: -0.5,0 0.5,0 ; 0,-0.5 0,0.5 ; -16.5,-16.5 -16.5,16.5 16.5,16.5 16.5,-16.5 -16.5,-16.5
3D body: height 2.6, standoff 0, extent -15.5,-15.5 15.5,15.5

## FG1156 [mm] "1156-Ball Fine Pitch Plastic Ball Grid Array (FG1156)"
height 2.6
pads (1156):
  round 0.5 smd: A1(-16.5,16.5) A2(-15.5,16.5) A3(-14.5,16.5) A4(-13.5,16.5) A5(-12.5,16.5) A6(-11.5,16.5) A7(-10.5,16.5) A8(-9.5,16.5) A9(-8.5,16.5) A10(-7.5,16.5) A11(-6.5,16.5) A12(-5.5,16.5) A13(-4.5,16.5) A14(-3.5,16.5) A15(-2.5,16.5) A16(-1.5,16.5) A17(-0.5,16.5) A18(0.5,16.5) A19(1.5,16.5) A20(2.5,16.5) A21(3.5,16.5) A22(4.5,16.5) A23(5.5,16.5) A24(6.5,16.5) A25(7.5,16.5) A26(8.5,16.5) A27(9.5,16.5) A28(10.5,16.5) A29(11.5,16.5) A30(12.5,16.5) A31(13.5,16.5) A32(14.5,16.5) A33(15.5,16.5) A34(16.5,16.5) AA1(-16.5,-3.5) AA2(-15.5,-3.5) AA3(-14.5,-3.5) AA4(-13.5,-3.5) AA5(-12.5,-3.5) AA6(-11.5,-3.5) AA7(-10.5,-3.5) AA8(-9.5,-3.5) AA9(-8.5,-3.5) AA10(-7.5,-3.5) AA11(-6.5,-3.5) AA12(-5.5,-3.5) AA13(-4.5,-3.5) AA14(-3.5,-3.5) AA15(-2.5,-3.5) AA16(-1.5,-3.5) AA17(-0.5,-3.5) AA18(0.5,-3.5) AA19(1.5,-3.5) AA20(2.5,-3.5) AA21(3.5,-3.5) AA22(4.5,-3.5) AA23(5.5,-3.5) AA24(6.5,-3.5) AA25(7.5,-3.5) AA26(8.5,-3.5) AA27(9.5,-3.5) AA28(10.5,-3.5) AA29(11.5,-3.5) AA30(12.5,-3.5) AA31(13.5,-3.5) AA32(14.5,-3.5) AA33(15.5,-3.5) AA34(16.5,-3.5) AB1(-16.5,-4.5) AB2(-15.5,-4.5) AB3(-14.5,-4.5) AB4(-13.5,-4.5) AB5(-12.5,-4.5) AB6(-11.5,-4.5) AB7(-10.5,-4.5) AB8(-9.5,-4.5) AB9(-8.5,-4.5) AB10(-7.5,-4.5) AB11(-6.5,-4.5) AB12(-5.5,-4.5) AB13(-4.5,-4.5) AB14(-3.5,-4.5) AB15(-2.5,-4.5) AB16(-1.5,-4.5) AB17(-0.5,-4.5) AB18(0.5,-4.5) AB19(1.5,-4.5) AB20(2.5,-4.5) AB21(3.5,-4.5) AB22(4.5,-4.5) AB23(5.5,-4.5) AB24(6.5,-4.5) AB25(7.5,-4.5) AB26(8.5,-4.5) AB27(9.5,-4.5) AB28(10.5,-4.5) AB29(11.5,-4.5) AB30(12.5,-4.5) AB31(13.5,-4.5) AB32(14.5,-4.5) AB33(15.5,-4.5) AB34(16.5,-4.5) AC1(-16.5,-5.5) AC2(-15.5,-5.5) AC3(-14.5,-5.5) AC4(-13.5,-5.5) AC5(-12.5,-5.5) AC6(-11.5,-5.5) AC7(-10.5,-5.5) AC8(-9.5,-5.5) AC9(-8.5,-5.5) AC10(-7.5,-5.5) AC11(-6.5,-5.5) AC12(-5.5,-5.5) AC13(-4.5,-5.5) AC14(-3.5,-5.5) AC15(-2.5,-5.5) AC16(-1.5,-5.5) AC17(-0.5,-5.5) AC18(0.5,-5.5) AC19(1.5,-5.5) AC20(2.5,-5.5) AC21(3.5,-5.5) AC22(4.5,-5.5) AC23(5.5,-5.5) AC24(6.5,-5.5) AC25(7.5,-5.5) AC26(8.5,-5.5) AC27(9.5,-5.5) AC28(10.5,-5.5) AC29(11.5,-5.5) AC30(12.5,-5.5) AC31(13.5,-5.5) AC32(14.5,-5.5) AC33(15.5,-5.5) AC34(16.5,-5.5) AD1(-16.5,-6.5) AD2(-15.5,-6.5) AD3(-14.5,-6.5) AD4(-13.5,-6.5) AD5(-12.5,-6.5) AD6(-11.5,-6.5) AD7(-10.5,-6.5) AD8(-9.5,-6.5) AD9(-8.5,-6.5) AD10(-7.5,-6.5) AD11(-6.5,-6.5) AD12(-5.5,-6.5) AD13(-4.5,-6.5) AD14(-3.5,-6.5) AD15(-2.5,-6.5) AD16(-1.5,-6.5) AD17(-0.5,-6.5) AD18(0.5,-6.5) AD19(1.5,-6.5) AD20(2.5,-6.5) AD21(3.5,-6.5) AD22(4.5,-6.5) AD23(5.5,-6.5) AD24(6.5,-6.5) AD25(7.5,-6.5) AD26(8.5,-6.5) AD27(9.5,-6.5) AD28(10.5,-6.5) AD29(11.5,-6.5) AD30(12.5,-6.5) AD31(13.5,-6.5) AD32(14.5,-6.5) AD33(15.5,-6.5) AD34(16.5,-6.5) AE1(-16.5,-7.5) AE2(-15.5,-7.5) AE3(-14.5,-7.5) AE4(-13.5,-7.5) AE5(-12.5,-7.5) AE6(-11.5,-7.5) AE7(-10.5,-7.5) AE8(-9.5,-7.5) AE9(-8.5,-7.5) AE10(-7.5,-7.5) AE11(-6.5,-7.5) AE12(-5.5,-7.5) AE13(-4.5,-7.5) AE14(-3.5,-7.5) AE15(-2.5,-7.5) AE16(-1.5,-7.5) AE17(-0.5,-7.5) AE18(0.5,-7.5) AE19(1.5,-7.5) AE20(2.5,-7.5) AE21(3.5,-7.5) AE22(4.5,-7.5) AE23(5.5,-7.5) AE24(6.5,-7.5) AE25(7.5,-7.5) AE26(8.5,-7.5) AE27(9.5,-7.5) AE28(10.5,-7.5) AE29(11.5,-7.5) AE30(12.5,-7.5) AE31(13.5,-7.5) AE32(14.5,-7.5) AE33(15.5,-7.5) AE34(16.5,-7.5) AF1(-16.5,-8.5) AF2(-15.5,-8.5) AF3(-14.5,-8.5) AF4(-13.5,-8.5) AF5(-12.5,-8.5) AF6(-11.5,-8.5) AF7(-10.5,-8.5) AF8(-9.5,-8.5) AF9(-8.5,-8.5) AF10(-7.5,-8.5) AF11(-6.5,-8.5) AF12(-5.5,-8.5) AF13(-4.5,-8.5) AF14(-3.5,-8.5) AF15(-2.5,-8.5) AF16(-1.5,-8.5) AF17(-0.5,-8.5) AF18(0.5,-8.5) AF19(1.5,-8.5) AF20(2.5,-8.5) AF21(3.5,-8.5) AF22(4.5,-8.5) AF23(5.5,-8.5) AF24(6.5,-8.5) AF25(7.5,-8.5) AF26(8.5,-8.5) AF27(9.5,-8.5) AF28(10.5,-8.5) AF29(11.5,-8.5) AF30(12.5,-8.5) AF31(13.5,-8.5) AF32(14.5,-8.5) AF33(15.5,-8.5) AF34(16.5,-8.5) AG1(-16.5,-9.5) AG2(-15.5,-9.5) AG3(-14.5,-9.5) AG4(-13.5,-9.5) AG5(-12.5,-9.5) AG6(-11.5,-9.5) AG7(-10.5,-9.5) AG8(-9.5,-9.5) AG9(-8.5,-9.5) AG10(-7.5,-9.5) AG11(-6.5,-9.5) AG12(-5.5,-9.5) AG13(-4.5,-9.5) AG14(-3.5,-9.5) AG15(-2.5,-9.5) AG16(-1.5,-9.5) AG17(-0.5,-9.5) AG18(0.5,-9.5) AG19(1.5,-9.5) AG20(2.5,-9.5) AG21(3.5,-9.5) AG22(4.5,-9.5) AG23(5.5,-9.5) AG24(6.5,-9.5) AG25(7.5,-9.5) AG26(8.5,-9.5) AG27(9.5,-9.5) AG28(10.5,-9.5) AG29(11.5,-9.5) AG30(12.5,-9.5) AG31(13.5,-9.5) AG32(14.5,-9.5) AG33(15.5,-9.5) AG34(16.5,-9.5) AH1(-16.5,-10.5) AH2(-15.5,-10.5) AH3(-14.5,-10.5) AH4(-13.5,-10.5) AH5(-12.5,-10.5) AH6(-11.5,-10.5) AH7(-10.5,-10.5) AH8(-9.5,-10.5) AH9(-8.5,-10.5) AH10(-7.5,-10.5) AH11(-6.5,-10.5) AH12(-5.5,-10.5) AH13(-4.5,-10.5) AH14(-3.5,-10.5) AH15(-2.5,-10.5) AH16(-1.5,-10.5) AH17(-0.5,-10.5) AH18(0.5,-10.5) AH19(1.5,-10.5) AH20(2.5,-10.5) AH21(3.5,-10.5) AH22(4.5,-10.5) AH23(5.5,-10.5) AH24(6.5,-10.5) AH25(7.5,-10.5) AH26(8.5,-10.5) AH27(9.5,-10.5) AH28(10.5,-10.5) AH29(11.5,-10.5) AH30(12.5,-10.5) AH31(13.5,-10.5) AH32(14.5,-10.5) AH33(15.5,-10.5) AH34(16.5,-10.5) AJ1(-16.5,-11.5) AJ2(-15.5,-11.5) AJ3(-14.5,-11.5) AJ4(-13.5,-11.5) AJ5(-12.5,-11.5) AJ6(-11.5,-11.5) AJ7(-10.5,-11.5) AJ8(-9.5,-11.5) AJ9(-8.5,-11.5) AJ10(-7.5,-11.5) AJ11(-6.5,-11.5) AJ12(-5.5,-11.5) AJ13(-4.5,-11.5) AJ14(-3.5,-11.5) AJ15(-2.5,-11.5) AJ16(-1.5,-11.5) AJ17(-0.5,-11.5) AJ18(0.5,-11.5) AJ19(1.5,-11.5) AJ20(2.5,-11.5) AJ21(3.5,-11.5) AJ22(4.5,-11.5) AJ23(5.5,-11.5) AJ24(6.5,-11.5) AJ25(7.5,-11.5) AJ26(8.5,-11.5) AJ27(9.5,-11.5) AJ28(10.5,-11.5) AJ29(11.5,-11.5) AJ30(12.5,-11.5) AJ31(13.5,-11.5) AJ32(14.5,-11.5) AJ33(15.5,-11.5) AJ34(16.5,-11.5) AK1(-16.5,-12.5) AK2(-15.5,-12.5) AK3(-14.5,-12.5) AK4(-13.5,-12.5) AK5(-12.5,-12.5) AK6(-11.5,-12.5) AK7(-10.5,-12.5) AK8(-9.5,-12.5) AK9(-8.5,-12.5) AK10(-7.5,-12.5) AK11(-6.5,-12.5) AK12(-5.5,-12.5) AK13(-4.5,-12.5) AK14(-3.5,-12.5) AK15(-2.5,-12.5) AK16(-1.5,-12.5) AK17(-0.5,-12.5) AK18(0.5,-12.5) AK19(1.5,-12.5) AK20(2.5,-12.5) AK21(3.5,-12.5) AK22(4.5,-12.5) AK23(5.5,-12.5) AK24(6.5,-12.5) AK25(7.5,-12.5) AK26(8.5,-12.5) AK27(9.5,-12.5) AK28(10.5,-12.5) AK29(11.5,-12.5) AK30(12.5,-12.5) AK31(13.5,-12.5) AK32(14.5,-12.5) AK33(15.5,-12.5) AK34(16.5,-12.5) AL1(-16.5,-13.5) AL2(-15.5,-13.5) AL3(-14.5,-13.5) AL4(-13.5,-13.5) AL5(-12.5,-13.5) AL6(-11.5,-13.5) AL7(-10.5,-13.5) AL8(-9.5,-13.5) AL9(-8.5,-13.5) AL10(-7.5,-13.5) AL11(-6.5,-13.5) AL12(-5.5,-13.5) AL13(-4.5,-13.5) AL14(-3.5,-13.5) AL15(-2.5,-13.5) AL16(-1.5,-13.5) AL17(-0.5,-13.5) AL18(0.5,-13.5) AL19(1.5,-13.5) AL20(2.5,-13.5) AL21(3.5,-13.5) AL22(4.5,-13.5) AL23(5.5,-13.5) AL24(6.5,-13.5) AL25(7.5,-13.5) AL26(8.5,-13.5) AL27(9.5,-13.5) AL28(10.5,-13.5) AL29(11.5,-13.5) AL30(12.5,-13.5) AL31(13.5,-13.5) AL32(14.5,-13.5) AL33(15.5,-13.5) AL34(16.5,-13.5) AM1(-16.5,-14.5) AM2(-15.5,-14.5) AM3(-14.5,-14.5) AM4(-13.5,-14.5) AM5(-12.5,-14.5) AM6(-11.5,-14.5) AM7(-10.5,-14.5) AM8(-9.5,-14.5) AM9(-8.5,-14.5) AM10(-7.5,-14.5) AM11(-6.5,-14.5) AM12(-5.5,-14.5) AM13(-4.5,-14.5) AM14(-3.5,-14.5) AM15(-2.5,-14.5) AM16(-1.5,-14.5) AM17(-0.5,-14.5) AM18(0.5,-14.5) AM19(1.5,-14.5) AM20(2.5,-14.5) AM21(3.5,-14.5) AM22(4.5,-14.5) AM23(5.5,-14.5) AM24(6.5,-14.5) AM25(7.5,-14.5) AM26(8.5,-14.5) AM27(9.5,-14.5) AM28(10.5,-14.5) AM29(11.5,-14.5) AM30(12.5,-14.5) AM31(13.5,-14.5) AM32(14.5,-14.5) AM33(15.5,-14.5) AM34(16.5,-14.5) AN1(-16.5,-15.5) AN2(-15.5,-15.5) AN3(-14.5,-15.5) AN4(-13.5,-15.5) AN5(-12.5,-15.5) AN6(-11.5,-15.5) AN7(-10.5,-15.5) AN8(-9.5,-15.5) AN9(-8.5,-15.5) AN10(-7.5,-15.5) AN11(-6.5,-15.5) AN12(-5.5,-15.5) AN13(-4.5,-15.5) AN14(-3.5,-15.5) AN15(-2.5,-15.5) AN16(-1.5,-15.5) AN17(-0.5,-15.5) AN18(0.5,-15.5) AN19(1.5,-15.5) AN20(2.5,-15.5) AN21(3.5,-15.5) AN22(4.5,-15.5) AN23(5.5,-15.5) AN24(6.5,-15.5) AN25(7.5,-15.5) AN26(8.5,-15.5) AN27(9.5,-15.5) AN28(10.5,-15.5) AN29(11.5,-15.5) AN30(12.5,-15.5) AN31(13.5,-15.5) AN32(14.5,-15.5) AN33(15.5,-15.5) AN34(16.5,-15.5) AP1(-16.5,-16.5) AP2(-15.5,-16.5) AP3(-14.5,-16.5) AP4(-13.5,-16.5) AP5(-12.5,-16.5) AP6(-11.5,-16.5) AP7(-10.5,-16.5) AP8(-9.5,-16.5) AP9(-8.5,-16.5) AP10(-7.5,-16.5) AP11(-6.5,-16.5) AP12(-5.5,-16.5) AP13(-4.5,-16.5) AP14(-3.5,-16.5) AP15(-2.5,-16.5) AP16(-1.5,-16.5) AP17(-0.5,-16.5) AP18(0.5,-16.5) AP19(1.5,-16.5) AP20(2.5,-16.5) AP21(3.5,-16.5) AP22(4.5,-16.5) AP23(5.5,-16.5) AP24(6.5,-16.5) AP25(7.5,-16.5) AP26(8.5,-16.5) AP27(9.5,-16.5) AP28(10.5,-16.5) AP29(11.5,-16.5) AP30(12.5,-16.5) AP31(13.5,-16.5) AP32(14.5,-16.5) AP33(15.5,-16.5) AP34(16.5,-16.5) B1(-16.5,15.5) B2(-15.5,15.5) B3(-14.5,15.5) B4(-13.5,15.5) B5(-12.5,15.5) B6(-11.5,15.5) B7(-10.5,15.5) B8(-9.5,15.5) B9(-8.5,15.5) B10(-7.5,15.5) B11(-6.5,15.5) B12(-5.5,15.5) B13(-4.5,15.5) B14(-3.5,15.5) B15(-2.5,15.5) B16(-1.5,15.5) B17(-0.5,15.5) B18(0.5,15.5) B19(1.5,15.5) B20(2.5,15.5) B21(3.5,15.5) B22(4.5,15.5) B23(5.5,15.5) B24(6.5,15.5) B25(7.5,15.5) B26(8.5,15.5) B27(9.5,15.5) B28(10.5,15.5) B29(11.5,15.5) B30(12.5,15.5) B31(13.5,15.5) B32(14.5,15.5) B33(15.5,15.5) B34(16.5,15.5) C1(-16.5,14.5) C2(-15.5,14.5) C3(-14.5,14.5) C4(-13.5,14.5) C5(-12.5,14.5) C6(-11.5,14.5) C7(-10.5,14.5) C8(-9.5,14.5) C9(-8.5,14.5) C10(-7.5,14.5) C11(-6.5,14.5) C12(-5.5,14.5) C13(-4.5,14.5) C14(-3.5,14.5) C15(-2.5,14.5) C16(-1.5,14.5) C17(-0.5,14.5) C18(0.5,14.5) C19(1.5,14.5) C20(2.5,14.5) C21(3.5,14.5) C22(4.5,14.5) C23(5.5,14.5) C24(6.5,14.5) C25(7.5,14.5) C26(8.5,14.5) C27(9.5,14.5) C28(10.5,14.5) C29(11.5,14.5) C30(12.5,14.5) C31(13.5,14.5) C32(14.5,14.5) C33(15.5,14.5) C34(16.5,14.5) D1(-16.5,13.5) D2(-15.5,13.5) D3(-14.5,13.5) D4(-13.5,13.5) D5(-12.5,13.5) D6(-11.5,13.5) D7(-10.5,13.5) D8(-9.5,13.5) D9(-8.5,13.5) D10(-7.5,13.5) D11(-6.5,13.5) D12(-5.5,13.5) D13(-4.5,13.5) D14(-3.5,13.5) D15(-2.5,13.5) D16(-1.5,13.5) D17(-0.5,13.5) D18(0.5,13.5) D19(1.5,13.5) D20(2.5,13.5) D21(3.5,13.5) D22(4.5,13.5) D23(5.5,13.5) D24(6.5,13.5) D25(7.5,13.5) D26(8.5,13.5) D27(9.5,13.5) D28(10.5,13.5) D29(11.5,13.5) D30(12.5,13.5) D31(13.5,13.5) D32(14.5,13.5) D33(15.5,13.5) D34(16.5,13.5) E1(-16.5,12.5) E2(-15.5,12.5) E3(-14.5,12.5) E4(-13.5,12.5) E5(-12.5,12.5) E6(-11.5,12.5) E7(-10.5,12.5) E8(-9.5,12.5) E9(-8.5,12.5) E10(-7.5,12.5) E11(-6.5,12.5) E12(-5.5,12.5) E13(-4.5,12.5) E14(-3.5,12.5) E15(-2.5,12.5) E16(-1.5,12.5) E17(-0.5,12.5) E18(0.5,12.5) E19(1.5,12.5) E20(2.5,12.5) E21(3.5,12.5) E22(4.5,12.5) E23(5.5,12.5) E24(6.5,12.5) E25(7.5,12.5) E26(8.5,12.5) E27(9.5,12.5) E28(10.5,12.5) E29(11.5,12.5) E30(12.5,12.5) E31(13.5,12.5) E32(14.5,12.5) E33(15.5,12.5) E34(16.5,12.5) F1(-16.5,11.5) F2(-15.5,11.5) F3(-14.5,11.5) F4(-13.5,11.5) F5(-12.5,11.5) F6(-11.5,11.5) F7(-10.5,11.5) F8(-9.5,11.5) F9(-8.5,11.5) F10(-7.5,11.5) F11(-6.5,11.5) F12(-5.5,11.5) F13(-4.5,11.5) F14(-3.5,11.5) F15(-2.5,11.5) F16(-1.5,11.5) F17(-0.5,11.5) F18(0.5,11.5) F19(1.5,11.5) F20(2.5,11.5) F21(3.5,11.5) F22(4.5,11.5) F23(5.5,11.5) F24(6.5,11.5) F25(7.5,11.5) F26(8.5,11.5) F27(9.5,11.5) F28(10.5,11.5) F29(11.5,11.5) F30(12.5,11.5) F31(13.5,11.5) F32(14.5,11.5) F33(15.5,11.5) F34(16.5,11.5) G1(-16.5,10.5) G2(-15.5,10.5) G3(-14.5,10.5) G4(-13.5,10.5) G5(-12.5,10.5) G6(-11.5,10.5) G7(-10.5,10.5) G8(-9.5,10.5) G9(-8.5,10.5) G10(-7.5,10.5) G11(-6.5,10.5) G12(-5.5,10.5) G13(-4.5,10.5) G14(-3.5,10.5) G15(-2.5,10.5) G16(-1.5,10.5) G17(-0.5,10.5) G18(0.5,10.5) G19(1.5,10.5) G20(2.5,10.5) G21(3.5,10.5) G22(4.5,10.5) G23(5.5,10.5) G24(6.5,10.5) G25(7.5,10.5) G26(8.5,10.5) G27(9.5,10.5) G28(10.5,10.5) G29(11.5,10.5) G30(12.5,10.5) G31(13.5,10.5) G32(14.5,10.5) G33(15.5,10.5) G34(16.5,10.5) H1(-16.5,9.5) H2(-15.5,9.5) H3(-14.5,9.5) H4(-13.5,9.5) H5(-12.5,9.5) H6(-11.5,9.5) H7(-10.5,9.5) H8(-9.5,9.5) H9(-8.5,9.5) H10(-7.5,9.5) H11(-6.5,9.5) H12(-5.5,9.5) H13(-4.5,9.5) H14(-3.5,9.5) H15(-2.5,9.5) H16(-1.5,9.5) H17(-0.5,9.5) H18(0.5,9.5) H19(1.5,9.5) H20(2.5,9.5) H21(3.5,9.5) H22(4.5,9.5) H23(5.5,9.5) H24(6.5,9.5) H25(7.5,9.5) H26(8.5,9.5) H27(9.5,9.5) H28(10.5,9.5) H29(11.5,9.5) H30(12.5,9.5) H31(13.5,9.5) H32(14.5,9.5) H33(15.5,9.5) H34(16.5,9.5) J1(-16.5,8.5) J2(-15.5,8.5) J3(-14.5,8.5) J4(-13.5,8.5) J5(-12.5,8.5) J6(-11.5,8.5) J7(-10.5,8.5) J8(-9.5,8.5) J9(-8.5,8.5) J10(-7.5,8.5) J11(-6.5,8.5) J12(-5.5,8.5) J13(-4.5,8.5) J14(-3.5,8.5) J15(-2.5,8.5) J16(-1.5,8.5) J17(-0.5,8.5) J18(0.5,8.5) J19(1.5,8.5) J20(2.5,8.5) J21(3.5,8.5) J22(4.5,8.5) J23(5.5,8.5) J24(6.5,8.5) J25(7.5,8.5) J26(8.5,8.5) J27(9.5,8.5) J28(10.5,8.5) J29(11.5,8.5) J30(12.5,8.5) J31(13.5,8.5) J32(14.5,8.5) J33(15.5,8.5) J34(16.5,8.5) K1(-16.5,7.5) K2(-15.5,7.5) K3(-14.5,7.5) K4(-13.5,7.5) K5(-12.5,7.5) K6(-11.5,7.5) K7(-10.5,7.5) K8(-9.5,7.5) K9(-8.5,7.5) K10(-7.5,7.5) K11(-6.5,7.5) K12(-5.5,7.5) K13(-4.5,7.5) K14(-3.5,7.5) K15(-2.5,7.5) K16(-1.5,7.5) K17(-0.5,7.5) K18(0.5,7.5) K19(1.5,7.5) K20(2.5,7.5) K21(3.5,7.5) K22(4.5,7.5) K23(5.5,7.5) K24(6.5,7.5) K25(7.5,7.5) K26(8.5,7.5) K27(9.5,7.5) K28(10.5,7.5) K29(11.5,7.5) K30(12.5,7.5) K31(13.5,7.5) K32(14.5,7.5) K33(15.5,7.5) K34(16.5,7.5) L1(-16.5,6.5) L2(-15.5,6.5) L3(-14.5,6.5) L4(-13.5,6.5) L5(-12.5,6.5) L6(-11.5,6.5) L7(-10.5,6.5) L8(-9.5,6.5) L9(-8.5,6.5) L10(-7.5,6.5) L11(-6.5,6.5) L12(-5.5,6.5) L13(-4.5,6.5) L14(-3.5,6.5) L15(-2.5,6.5) L16(-1.5,6.5) L17(-0.5,6.5) L18(0.5,6.5) L19(1.5,6.5) L20(2.5,6.5) L21(3.5,6.5) L22(4.5,6.5) L23(5.5,6.5) L24(6.5,6.5) L25(7.5,6.5) L26(8.5,6.5) L27(9.5,6.5) L28(10.5,6.5) L29(11.5,6.5) L30(12.5,6.5) L31(13.5,6.5) L32(14.5,6.5) L33(15.5,6.5) L34(16.5,6.5) M1(-16.5,5.5) M2(-15.5,5.5) M3(-14.5,5.5) M4(-13.5,5.5) M5(-12.5,5.5) M6(-11.5,5.5) M7(-10.5,5.5) M8(-9.5,5.5) M9(-8.5,5.5) M10(-7.5,5.5) M11(-6.5,5.5) M12(-5.5,5.5) M13(-4.5,5.5) M14(-3.5,5.5) M15(-2.5,5.5) M16(-1.5,5.5) M17(-0.5,5.5) M18(0.5,5.5) M19(1.5,5.5) M20(2.5,5.5) M21(3.5,5.5) M22(4.5,5.5) M23(5.5,5.5) M24(6.5,5.5) M25(7.5,5.5) M26(8.5,5.5) M27(9.5,5.5) M28(10.5,5.5) M29(11.5,5.5) M30(12.5,5.5) M31(13.5,5.5) M32(14.5,5.5) M33(15.5,5.5) M34(16.5,5.5) N1(-16.5,4.5) N2(-15.5,4.5) N3(-14.5,4.5) N4(-13.5,4.5) N5(-12.5,4.5) N6(-11.5,4.5) N7(-10.5,4.5) N8(-9.5,4.5) N9(-8.5,4.5) N10(-7.5,4.5) N11(-6.5,4.5) N12(-5.5,4.5) N13(-4.5,4.5) N14(-3.5,4.5) N15(-2.5,4.5) N16(-1.5,4.5) N17(-0.5,4.5) N18(0.5,4.5) N19(1.5,4.5) N20(2.5,4.5) N21(3.5,4.5) N22(4.5,4.5) N23(5.5,4.5) N24(6.5,4.5) N25(7.5,4.5) N26(8.5,4.5) N27(9.5,4.5) N28(10.5,4.5) N29(11.5,4.5) N30(12.5,4.5) N31(13.5,4.5) N32(14.5,4.5) N33(15.5,4.5) N34(16.5,4.5) P1(-16.5,3.5) P2(-15.5,3.5) P3(-14.5,3.5) P4(-13.5,3.5) P5(-12.5,3.5) P6(-11.5,3.5) P7(-10.5,3.5) P8(-9.5,3.5) P9(-8.5,3.5) P10(-7.5,3.5) P11(-6.5,3.5) P12(-5.5,3.5) P13(-4.5,3.5) P14(-3.5,3.5) P15(-2.5,3.5) P16(-1.5,3.5) P17(-0.5,3.5) P18(0.5,3.5) P19(1.5,3.5) P20(2.5,3.5) P21(3.5,3.5) P22(4.5,3.5) P23(5.5,3.5) P24(6.5,3.5) P25(7.5,3.5) P26(8.5,3.5) P27(9.5,3.5) P28(10.5,3.5) P29(11.5,3.5) P30(12.5,3.5) P31(13.5,3.5) P32(14.5,3.5) P33(15.5,3.5) P34(16.5,3.5) R1(-16.5,2.5) R2(-15.5,2.5) R3(-14.5,2.5) R4(-13.5,2.5) R5(-12.5,2.5) R6(-11.5,2.5) R7(-10.5,2.5) R8(-9.5,2.5) R9(-8.5,2.5) R10(-7.5,2.5) R11(-6.5,2.5) R12(-5.5,2.5) R13(-4.5,2.5) R14(-3.5,2.5) R15(-2.5,2.5) R16(-1.5,2.5) R17(-0.5,2.5) R18(0.5,2.5) R19(1.5,2.5) R20(2.5,2.5) R21(3.5,2.5) R22(4.5,2.5) R23(5.5,2.5) R24(6.5,2.5) R25(7.5,2.5) R26(8.5,2.5) R27(9.5,2.5) R28(10.5,2.5) R29(11.5,2.5) R30(12.5,2.5) R31(13.5,2.5) R32(14.5,2.5) R33(15.5,2.5) R34(16.5,2.5) T1(-16.5,1.5) T2(-15.5,1.5) T3(-14.5,1.5) T4(-13.5,1.5) T5(-12.5,1.5) T6(-11.5,1.5) T7(-10.5,1.5) T8(-9.5,1.5) T9(-8.5,1.5) T10(-7.5,1.5) T11(-6.5,1.5) T12(-5.5,1.5) T13(-4.5,1.5) T14(-3.5,1.5) T15(-2.5,1.5) T16(-1.5,1.5) T17(-0.5,1.5) T18(0.5,1.5) T19(1.5,1.5) T20(2.5,1.5) T21(3.5,1.5) T22(4.5,1.5) T23(5.5,1.5) T24(6.5,1.5) T25(7.5,1.5) T26(8.5,1.5) T27(9.5,1.5) T28(10.5,1.5) T29(11.5,1.5) T30(12.5,1.5) T31(13.5,1.5) T32(14.5,1.5) T33(15.5,1.5) T34(16.5,1.5) U1(-16.5,0.5) U2(-15.5,0.5) U3(-14.5,0.5) U4(-13.5,0.5) U5(-12.5,0.5) U6(-11.5,0.5) U7(-10.5,0.5) U8(-9.5,0.5) U9(-8.5,0.5) U10(-7.5,0.5) U11(-6.5,0.5) U12(-5.5,0.5) U13(-4.5,0.5) U14(-3.5,0.5) U15(-2.5,0.5) U16(-1.5,0.5) U17(-0.5,0.5) U18(0.5,0.5) U19(1.5,0.5) U20(2.5,0.5) U21(3.5,0.5) U22(4.5,0.5) U23(5.5,0.5) U24(6.5,0.5) U25(7.5,0.5) U26(8.5,0.5) U27(9.5,0.5) U28(10.5,0.5) U29(11.5,0.5) U30(12.5,0.5) U31(13.5,0.5) U32(14.5,0.5) U33(15.5,0.5) U34(16.5,0.5) V1(-16.5,-0.5) V2(-15.5,-0.5) V3(-14.5,-0.5) V4(-13.5,-0.5) V5(-12.5,-0.5) V6(-11.5,-0.5) V7(-10.5,-0.5) V8(-9.5,-0.5) V9(-8.5,-0.5) V10(-7.5,-0.5) V11(-6.5,-0.5) V12(-5.5,-0.5) V13(-4.5,-0.5) V14(-3.5,-0.5) V15(-2.5,-0.5) V16(-1.5,-0.5) V17(-0.5,-0.5) V18(0.5,-0.5) V19(1.5,-0.5) V20(2.5,-0.5) V21(3.5,-0.5) V22(4.5,-0.5) V23(5.5,-0.5) V24(6.5,-0.5) V25(7.5,-0.5) V26(8.5,-0.5) V27(9.5,-0.5) V28(10.5,-0.5) V29(11.5,-0.5) V30(12.5,-0.5) V31(13.5,-0.5) V32(14.5,-0.5) V33(15.5,-0.5) V34(16.5,-0.5) W1(-16.5,-1.5) W2(-15.5,-1.5) W3(-14.5,-1.5) W4(-13.5,-1.5) W5(-12.5,-1.5) W6(-11.5,-1.5) W7(-10.5,-1.5) W8(-9.5,-1.5) W9(-8.5,-1.5) W10(-7.5,-1.5) W11(-6.5,-1.5) W12(-5.5,-1.5) W13(-4.5,-1.5) W14(-3.5,-1.5) W15(-2.5,-1.5) W16(-1.5,-1.5) W17(-0.5,-1.5) W18(0.5,-1.5) W19(1.5,-1.5) W20(2.5,-1.5) W21(3.5,-1.5) W22(4.5,-1.5) W23(5.5,-1.5) W24(6.5,-1.5) W25(7.5,-1.5) W26(8.5,-1.5) W27(9.5,-1.5) W28(10.5,-1.5) W29(11.5,-1.5) W30(12.5,-1.5) W31(13.5,-1.5) W32(14.5,-1.5) W33(15.5,-1.5) W34(16.5,-1.5) Y1(-16.5,-2.5) Y2(-15.5,-2.5) Y3(-14.5,-2.5) Y4(-13.5,-2.5) Y5(-12.5,-2.5) Y6(-11.5,-2.5) Y7(-10.5,-2.5) Y8(-9.5,-2.5) Y9(-8.5,-2.5) Y10(-7.5,-2.5) Y11(-6.5,-2.5) Y12(-5.5,-2.5) Y13(-4.5,-2.5) Y14(-3.5,-2.5) Y15(-2.5,-2.5) Y16(-1.5,-2.5) Y17(-0.5,-2.5) Y18(0.5,-2.5) Y19(1.5,-2.5) Y20(2.5,-2.5) Y21(3.5,-2.5) Y22(4.5,-2.5) Y23(5.5,-2.5) Y24(6.5,-2.5) Y25(7.5,-2.5) Y26(8.5,-2.5) Y27(9.5,-2.5) Y28(10.5,-2.5) Y29(11.5,-2.5) Y30(12.5,-2.5) Y31(13.5,-2.5) Y32(14.5,-2.5) Y33(15.5,-2.5) Y34(16.5,-2.5)
Top Overlay:
  circle w0.25: c-18.15,16.5 r0.125
  region: -16.5,17.5 -17.5,16.5 -17.5,17.5
  lines w0.2: -17.5,16.5 -16.5,17.5 ; -17.5,-17.5 -17.5,17.5 17.5,17.5 17.5,-17.5 -17.5,-17.5
Mechanical 13:
  lines w0.1: -17.5,-17.5 -17.5,17.5 17.5,17.5 17.5,-17.5 -17.5,-17.5
Mechanical 15:
  lines w0.1: -0.5,0 0.5,0 ; 0,-0.5 0,0.5 ; -18.5,-18.5 -18.5,18.5 18.5,18.5 18.5,-18.5 -18.5,-18.5
3D body: height 2.6, standoff 0, extent -17.5,-17.5 17.5,17.5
